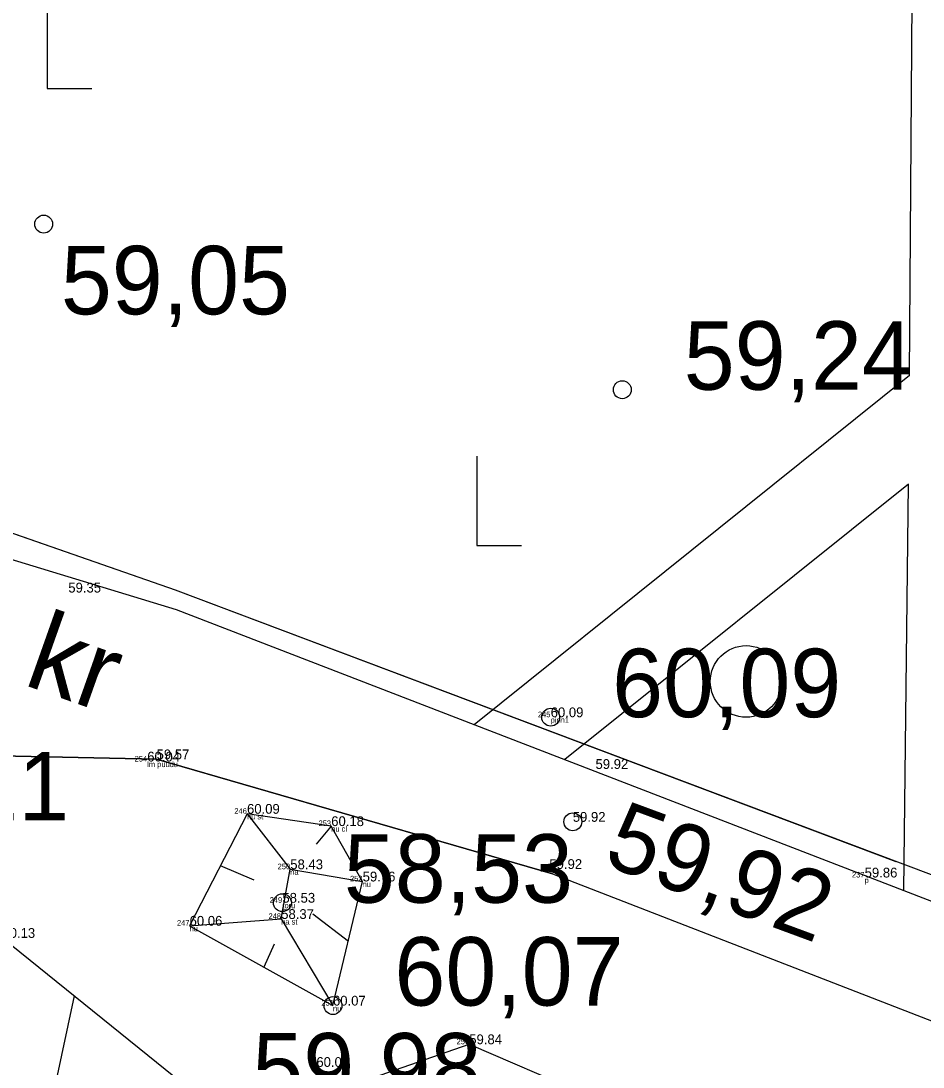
# Model space of a CAD drawing. Extents: x 700746 to 706058, y 6570320 to 6580460.
# Drawn here: x 702817.13 to 702849.42, y 6577305.34 to 6577342.76 of the extents above; entities that cross this region are included whole.
import ezdxf

# ---------------------------------------------------------------- set-up
doc = ezdxf.new("R2010")
doc.units = 0
for name, color, linetype in [('HALJASTUS', 7, 'Continuous'), ('KORGUS-EH2000', 7, 'Continuous'), ('MOOTKOOD', 7, 'Continuous'), ('MOOTKORG-EH2000', 7, 'Continuous'), ('MOOTNR', 7, 'Continuous'), ('RELJEEF', 7, 'Continuous'), ('TEE', 7, 'Continuous')]:
    doc.layers.add(name, color=color, linetype=linetype)

msp = doc.modelspace()

# ---------------------------------------------------------------- linework, layer by layer
at = {"layer": 'HALJASTUS'}
for p, q in [((702818.068, 6577343.544), (702818.068, 6577340.344)), ((702818.068, 6577340.344), (702819.668, 6577340.344)), ((702833.441, 6577327.193), (702833.441, 6577323.993)), ((702833.441, 6577323.993), (702835.041, 6577323.993))]:
    msp.add_line(p, q, dxfattribs=at)
for points in [[(702866.492, 6577335.901), (702865.472, 6577329.038), (702857.449, 6577309.3), (702822.656, 6577322.392), (702757.35, 6577345.153), (702769.898, 6577352.736), (702805.62, 6577368.998), (702829, 6577378.914), (702840.868, 6577380.666), (702854.366, 6577378.922)], [(702848.453, 6577312.685), (702822.656, 6577322.392), (702794.555, 6577332.186)]]:
    msp.add_lwpolyline(points, dxfattribs=at)
msp.add_circle((702843.083, 6577319.133), 1.28, dxfattribs=at)
at = {"layer": 'KORGUS-EH2000'}
for centre, radius in [((702817.942, 6577335.493), 0.32), ((702838.653, 6577329.567), 0.32), ((702836.089, 6577317.853), 0.32), ((702836.88, 6577314.112), 0.32), ((702826.487, 6577311.217), 0.32), ((702828.297, 6577307.537), 0.32), ((702827.703, 6577305.344), 0.05)]:
    msp.add_circle(centre, radius, dxfattribs=at)
at = {"layer": 'RELJEEF'}
for p, q in [((702828.234, 6577313.958), (702827.694, 6577313.315)), ((702825.472, 6577312.028), (702824.268, 6577312.542)), ((702827.577, 6577310.82), (702828.848, 6577309.84)), ((702826.193, 6577309.728), (702825.827, 6577308.912)), ((702818.363, 6577304.705), (702819.04, 6577307.883))]:
    msp.add_line(p, q, dxfattribs=at)
for points in [[(702788.78, 6577310.428), (702790.298, 6577313.542), (702800.869, 6577315.888), (702808.947, 6577316.567), (702816.466, 6577309.96), (702824.577, 6577303.416)], [(702825.221, 6577314.399), (702823.166, 6577310.394), (702828.297, 6577307.537), (702829.359, 6577311.978), (702828.234, 6577313.958), (702825.221, 6577314.399)], [(702825.221, 6577314.399), (702826.769, 6577312.415), (702829.359, 6577311.978)], [(702826.444, 6577310.636), (702826.769, 6577312.415)], [(702823.166, 6577310.394), (702826.444, 6577310.636), (702828.297, 6577307.537)], [(702820.373, 6577296.135), (702824.577, 6577303.416), (702828.415, 6577304.5), (702833.175, 6577306.155), (702841.265, 6577302.671), (702849.267, 6577301.128), (702855.4, 6577299.32), (702857.62, 6577299.44)]]:
    msp.add_lwpolyline(points, dxfattribs=at)
at = {"layer": 'TEE'}
for points in [[(702848.937, 6577330.072), (702849.028, 6577343.509), (702847.854, 6577357.252), (702846.842, 6577367.64), (702845.672, 6577372.753), (702843.602, 6577380.945)], [(702794.886, 6577330.593), (702799.954, 6577328.622), (702822.681, 6577321.702), (702855.964, 6577308.865)], [(702848.937, 6577330.072), (702833.356, 6577317.585)], [(702848.895, 6577326.194), (702836.594, 6577316.336)], [(702848.727, 6577311.656), (702848.895, 6577326.194)], [(702709.101, 6577280.997), (702707.813, 6577293.543), (702712.729, 6577298.162), (702723.023, 6577304.401), (702734.686, 6577307.203), (702773.811, 6577312.447), (702801.201, 6577316.79), (702821.985, 6577316.348), (702836.158, 6577312.247), (702853.721, 6577305.446)], [(702836.158, 6577312.247), (702821.985, 6577316.348), (702801.201, 6577316.79)]]:
    msp.add_lwpolyline(points, dxfattribs=at)

# ---------------------------------------------------------------- texts
at = {"layer": 'KORGUS-EH2000'}
for s, p in [('59,05', (702818.559, 6577332.265)), ('59,24', (702840.853, 6577329.567)), ('60,09', (702838.289, 6577317.853)), ('59,21', (702810.658, 6577314.159)), ('58,53', (702828.687, 6577311.217)), ('60,07', (702830.497, 6577307.537)), ('59,98', (702825.413, 6577304.104))]:
    msp.add_text(s, height=2.45, dxfattribs=at).set_placement(p)
msp.add_text('59,92', height=2.45, rotation=339.7243, dxfattribs=at).set_placement((702837.907, 6577312.607))
at = {"layer": 'MOOTKOOD'}
for s, p in [('pinn1', (702836.089, 6577317.653)), ('lm puudu', (702821.65, 6577316.068)), ('nu st', (702825.221, 6577314.199)), ('nu cl', (702828.234, 6577313.758)), ('na', (702826.769, 6577312.215)), ('p', (702847.326, 6577311.919)), ('nu', (702829.359, 6577311.778)), ('toru', (702826.487, 6577311.017)), ('na st', (702826.444, 6577310.436)), ('nu', (702823.166, 6577310.194)), ('nu', (702828.297, 6577307.337)), ('a', (702833.175, 6577305.955))]:
    msp.add_text(s, height=0.2, dxfattribs=at).set_placement(p)
at = {"layer": 'MOOTKORG-EH2000'}
for s, p in [('59.35', (702818.824, 6577322.313)), ('60.09', (702836.089, 6577317.853)), ('60.04', (702821.65, 6577316.268)), ('59.57', (702821.985, 6577316.348)), ('59.92', (702837.694, 6577316.003)), ('60.09', (702825.221, 6577314.399)), ('60.18', (702828.234, 6577313.958)), ('59.92', (702836.88, 6577314.112)), ('58.43', (702826.769, 6577312.415)), ('59.92', (702836.043, 6577312.424)), ('59.86', (702847.326, 6577312.119)), ('59.76', (702829.359, 6577311.978)), ('58.53', (702826.487, 6577311.217)), ('58.37', (702826.444, 6577310.636)), ('60.06', (702823.166, 6577310.394)), ('60.13', (702816.466, 6577309.96)), ('60.07', (702828.297, 6577307.537)), ('59.84', (702833.175, 6577306.155)), ('60.09', (702827.703, 6577305.344))]:
    msp.add_text(s, height=0.35, dxfattribs=at).set_placement(p)
at = {"layer": 'MOOTNR'}
for s, p in [('245', (702835.634, 6577317.853)), ('254', (702821.198, 6577316.268)), ('246', (702824.768, 6577314.399)), ('253', (702827.781, 6577313.958)), ('250', (702826.316, 6577312.415)), ('252', (702828.908, 6577311.978)), ('237', (702846.873, 6577312.119)), ('249', (702826.033, 6577311.217)), ('247', (702822.713, 6577310.394)), ('248', (702825.99, 6577310.636)), ('251', (702827.882, 6577307.537)), ('256', (702832.722, 6577306.155))]:
    msp.add_text(s, height=0.2, dxfattribs=at).set_placement(p)
at = {"layer": 'TEE'}
msp.add_text('kr', height=2.8, rotation=340.4833, dxfattribs=at).set_placement((702817.161, 6577319.035))

doc.saveas('drawing.dxf')
